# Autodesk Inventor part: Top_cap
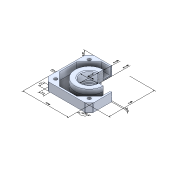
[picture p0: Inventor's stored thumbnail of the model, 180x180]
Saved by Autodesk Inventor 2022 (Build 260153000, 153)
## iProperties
Created: 2020-10
Part Number: Top_cap
Material: Generico
Document SubType Name: Modeling
Designer: admin
Density: 1 g/cm^3
Appearance: Default
Author: admin
Sending System: SolidWorks 2020
Last Author: Simon
Last Saved: 2020-10-31
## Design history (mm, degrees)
node "Annotazioni"
  node "Quota lineare 1" dims "d2" = 42 (derived), "d29" = 7.68128 (derived)
  node "Quota lineare 2" dims "d5" = 42 (derived), "d29" = 7.68128 (derived)
  node "Quota lineare 3" dims "d7" = 8 (derived), "d29" = 7.68128 (derived)
  node "Quota diametro 1" dims "d9" = 9 (derived), "d29" = 7.68128 (derived)
  node "Quota diametro 2" dims "d11" = 10 (derived), "d29" = 7.68128 (derived)
  node "Quota diametro 3" dims "d13" = 21.5 (derived), "d29" = 7.68128 (derived)
  node "Quota angolare 1" dims "d16" = 135 deg (derived), "d29" = 7.68128 (derived)
  node "Quota diametro 4" dims "d18" = 12 (derived), "d29" = 7.68128 (derived)
  node "Quota diametro 5" dims "d20" = 16 (derived), "d29" = 7.68128 (derived)
  node "Quota diametro 6" dims "d22" = 17.5 (derived), "d29" = 7.68128 (derived)
  node "Quota radiale 1" dims "d24" = 13 (derived), "d29" = 7.68128 (derived)
  node "Quota lineare 4" dims "d26" = 5.11469 (derived), "d29" = 7.68128 (derived)
  node "Quota lineare 5" dims "d28" = 5.11469 (derived), "d29" = 7.68128 (derived)
  node "Quota lineare 6" dims "d29" = 7.68128 (derived), "d31" = 2 (derived)
  node "Quota lineare 7" dims "d29" = 7.68128 (derived), "d32" = 1 (derived)
fillet "Fillet4"
node "Solido1"
other parameters: "d0" = 6.93847 (derived), "d1" = 7.89627 (derived), "d10" = 35.40108 (derived), "d12" = 31.09742 (derived), "d14" = 5.0818 (derived), "d15" = 0.84157 (derived), "d17" = 31.33322 (derived), "d19" = 15.82524 (derived), "d21" = 31.18508 (derived), "d23" = 31.06324 (derived), "d25" = 9.51676 (derived), "d27" = 0.91927 (derived), "d3" = 9.31564 (derived), "d30" = 2.29443 (derived), "d4" = 2.17137 (derived), "d6" = 5.37399 (derived), "d8" = 23.16943 (derived)
